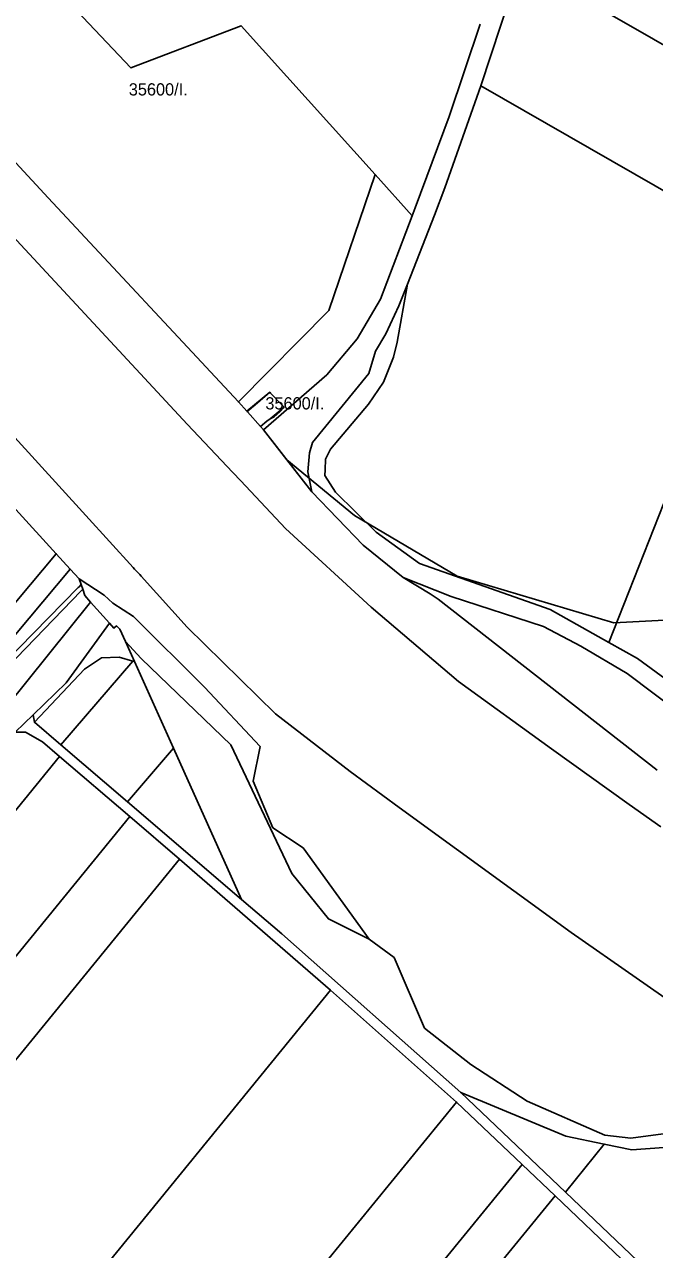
# Model space of a CAD drawing. Extents: x -545779 to -541342, y -1153413 to -1149956.
# Drawn here: x -543101 to -542843, y -1150751 to -1150249 of the extents above; entities that cross this region are included whole.
import ezdxf

# ---------------------------------------------------------------- set-up
doc = ezdxf.new("R2010")
doc.units = 0
for name, color, linetype in [('95560013', 7, 'Continuous'), ('95610013', 7, 'Continuous'), ('95630013', 7, 'Continuous'), ('95640013', 7, 'Continuous'), ('95660013', 7, 'Continuous')]:
    doc.layers.add(name, color=color, linetype=linetype)

msp = doc.modelspace()

# ---------------------------------------------------------------- linework, layer by layer
at = {"layer": '95560013'}
for points in [[(-543223.32, -1150177.07), (-543227.35, -1150172.67), (-543219.01, -1150174.06), (-543216.16, -1150173.5), (-543207.09, -1150171.73), (-543187.68, -1150162.8), (-543165.76, -1150152.71), (-543057.62, -1150266.96), (-543012.33, -1150249.67), (-542957.48, -1150310.69), (-542976.41, -1150366.39), (-543013.48, -1150403.82), (-543091.46, -1150320.27), (-543179.45, -1150224.97)], [(-542897.56, -1150224), (-542891.21, -1150204.63), (-542782.39, -1150267.04), (-542673.59, -1150329.44), (-542680.59, -1150348.45), (-542789.08, -1150286.22)], [(-542789.08, -1150286.22), (-542680.59, -1150348.45), (-542698.75, -1150397.83), (-542806.43, -1150336.07), (-542914.11, -1150274.31), (-542897.56, -1150224)], [(-542885.74, -1150488.88), (-542939.27, -1150470.05), (-542957.08, -1150457.18), (-542973.67, -1150440.8), (-542978.05, -1150433.99), (-542977.98, -1150431.6), (-542977.86, -1150427.24), (-542975.75, -1150423.15), (-542960.11, -1150404.77), (-542954.03, -1150395.7), (-542949.96, -1150385.51), (-542948.44, -1150379.28), (-542944.25, -1150355.53), (-542933.12, -1150327.25), (-542928.95, -1150316.13), (-542914.11, -1150274.31), (-542806.43, -1150336.07), (-542698.75, -1150397.83), (-542722.86, -1150463.35), (-542823.35, -1150405.71), (-542839.07, -1150445.37), (-542861.66, -1150502.34)], [(-543009.79, -1150407.92), (-543010.11, -1150407.57), (-543000.66, -1150399.9), (-543007.6, -1150405.91)], [(-543000.33, -1150400.24), (-542996.07, -1150404.62), (-542994.75, -1150405.99), (-543000.54, -1150410.75), (-543001.78, -1150411.78), (-543004.38, -1150413.91), (-543009.79, -1150407.92), (-543007.6, -1150405.91), (-543000.66, -1150399.9)], [(-543104.73, -1150447.88), (-543088.15, -1150466.06), (-543162.68, -1150554.86), (-543237.21, -1150643.67), (-543254.82, -1150626.72), (-543179.78, -1150537.3)], [(-542763.51, -1150562.3), (-542783.62, -1150552.52), (-542817.82, -1150532.5), (-542849.86, -1150508.94), (-542861.66, -1150502.34), (-542839.07, -1150445.37), (-542737.65, -1150503.54), (-542758.53, -1150560.29)], [(-543082.43, -1150472.34), (-543156.78, -1150560.93), (-543231.13, -1150649.52), (-543237.21, -1150643.67), (-543162.68, -1150554.86), (-543088.15, -1150466.06)], [(-543111.12, -1150513.04), (-543173.2, -1150597.05), (-543217.86, -1150645.08), (-543224.74, -1150652.49), (-543226.31, -1150654.16), (-543231.13, -1150649.52), (-543156.78, -1150560.93), (-543082.43, -1150472.34), (-543078.75, -1150476.37), (-543077.94, -1150478.69), (-543078.97, -1150479.78), (-543079.12, -1150479.93), (-543109.47, -1150510.9)], [(-543126.41, -1150566.98), (-543104.97, -1150539.21), (-543103.96, -1150539.21), (-543100.81, -1150539.2), (-543093.81, -1150543.17), (-543086.79, -1150549.18), (-543177.34, -1150659.99), (-543267.88, -1150770.8), (-543358.43, -1150881.61), (-543380.51, -1150876.41), (-543328.86, -1150811.29), (-543290.26, -1150766.2), (-543226.11, -1150690.02), (-543182.54, -1150636.07)], [(-543058.06, -1150573.75), (-543144.54, -1150679.58), (-543231.02, -1150785.42), (-543317.5, -1150891.25), (-543358.43, -1150881.61), (-543267.88, -1150770.8), (-543177.34, -1150659.99), (-543086.79, -1150549.18)], [(-543163.06, -1150744.64), (-543288.45, -1150898.09), (-543317.5, -1150891.25), (-543231.02, -1150785.42), (-543144.54, -1150679.58), (-543058.06, -1150573.75), (-543037.67, -1150591.19)], [(-543163.06, -1150744.64), (-543037.67, -1150591.19), (-542975.69, -1150644.9), (-543087.67, -1150781.95), (-543199.66, -1150919), (-543288.45, -1150898.09)], [(-543024.52, -1150813.68), (-543124.95, -1150936.58), (-543199.66, -1150919), (-543087.67, -1150781.95), (-542975.69, -1150644.9), (-542924.06, -1150690.74)], [(-542897.18, -1150716.29), (-542991.04, -1150831.15), (-543084.9, -1150946.01), (-543124.95, -1150936.58), (-543024.52, -1150813.68), (-542924.06, -1150690.74)], [(-543064.8, -1150950.74), (-543084.9, -1150946.01), (-542991.04, -1150831.15), (-542897.18, -1150716.29), (-542883.7, -1150729.1), (-542974.25, -1150839.92)], [(-542856.45, -1150755.01), (-542940.33, -1150857.67), (-543024.19, -1150960.3), (-543064.8, -1150950.74), (-542974.25, -1150839.92), (-542883.7, -1150729.1)]]:
    msp.add_lwpolyline(points, close=True, dxfattribs=at)
at = {"layer": '95610013'}
for points in [[(-543045.89, -1150516.18), (-543053.34, -1150509.02), (-543059.81, -1150502.04), (-543062.08, -1150497), (-543063.52, -1150495.61), (-543064.51, -1150496.55), (-543066.32, -1150494.52), (-543074.08, -1150485.82), (-543076.39, -1150483.13), (-543077.28, -1150480.58), (-543077.94, -1150478.69), (-543078.75, -1150476.37), (-543068.55, -1150482.98), (-543064.95, -1150486.26), (-543056.47, -1150491.74), (-543027.35, -1150520.68), (-543004.61, -1150545.08), (-543007.41, -1150559.24), (-542999.35, -1150578.34), (-542987.02, -1150586.47), (-542959.84, -1150623.97), (-542976.63, -1150615.62), (-542991.64, -1150597.02), (-543016.57, -1150544.34)], [(-543076.62, -1150513.27), (-543069.62, -1150508.7), (-543062.37, -1150508.36), (-543056.79, -1150509.99), (-543086.23, -1150544.4), (-543097.12, -1150535.08)], [(-543056.14, -1150510.18), (-543040.16, -1150545.65), (-543059, -1150567.68), (-543086.23, -1150544.4), (-543056.79, -1150509.99)], [(-543059, -1150567.68), (-543040.16, -1150545.65), (-543012.19, -1150607.72)], [(-542879.33, -1150704.7), (-542863.52, -1150707.95), (-542879.48, -1150727.6), (-542922.39, -1150686.8)], [(-542852.21, -1150710.28), (-542792.22, -1150705.95), (-542840.86, -1150764.31), (-542879.48, -1150727.6), (-542863.52, -1150707.95)]]:
    msp.add_lwpolyline(points, close=True, dxfattribs=at)
at = {"layer": '95630013'}
for points in [[(-542797.14, -1150676.99), (-542877.1, -1150621.25), (-542947.61, -1150569.95), (-542967.7, -1150555.26), (-542998.29, -1150531.61), (-543034.45, -1150496.06), (-543053.37, -1150475.24), (-543053.95, -1150474.59), (-543056.04, -1150472.29), (-543056.63, -1150471.65), (-543076, -1150450.32), (-543155.13, -1150363.61), (-543234.26, -1150276.9), (-543338.6, -1150169.04)], [(-543188.54, -1150247.11), (-543111.5, -1150330.01), (-543034.47, -1150412.91), (-543015.84, -1150432.69), (-543015.26, -1150433.31), (-543013.1, -1150435.6), (-543012.54, -1150436.2), (-542994.14, -1150455.73), (-542959.14, -1150487.92), (-542923.23, -1150518.4), (-542885.11, -1150545.91), (-542853.27, -1150568.8), (-542840.3, -1150577.96)]]:
    msp.add_lwpolyline(points, dxfattribs=at)
at = {"layer": '95640013'}
for points in [[(-542914.41, -1150249.01), (-542927.06, -1150286.9), (-542941.11, -1150324.36), (-542942.32, -1150327.56), (-542957.48, -1150310.69), (-543012.33, -1150249.67), (-543057.62, -1150266.96), (-543165.76, -1150152.71)], [(-543338.6, -1150169.04), (-543234.26, -1150276.9), (-543155.13, -1150363.61), (-543076, -1150450.32), (-543056.63, -1150471.65), (-543056.04, -1150472.29), (-543053.95, -1150474.59), (-543053.37, -1150475.24), (-543034.45, -1150496.06), (-542998.29, -1150531.61), (-542967.7, -1150555.26), (-542947.61, -1150569.95), (-542877.1, -1150621.25), (-542797.14, -1150676.99)], [(-543179.45, -1150224.97), (-543091.46, -1150320.27), (-543013.48, -1150403.82), (-543010.11, -1150407.57), (-543009.79, -1150407.92), (-543004.38, -1150413.91), (-543003.17, -1150415.25), (-542983.39, -1150440.67), (-542962.35, -1150462.51), (-542945.93, -1150475.79), (-542934.91, -1150482.45), (-542931.65, -1150484.68), (-542841.86, -1150554.66)], [(-542897.56, -1150224), (-542914.11, -1150274.31), (-542928.95, -1150316.13), (-542933.12, -1150327.25), (-542944.25, -1150355.53), (-542947.8, -1150364.52), (-542953.1, -1150375.9), (-542957.36, -1150383.09), (-542960.1, -1150392.22), (-542983.11, -1150420.46), (-542984.39, -1150424.73), (-542985.04, -1150432.41), (-542983.39, -1150440.67), (-543003.17, -1150415.25), (-542977.28, -1150392.72), (-542964.77, -1150377.98), (-542955.27, -1150361.66), (-542942.32, -1150327.56), (-542941.11, -1150324.36), (-542927.06, -1150286.9), (-542914.41, -1150249.01)], [(-542840.3, -1150577.96), (-542853.27, -1150568.8), (-542885.11, -1150545.91), (-542923.23, -1150518.4), (-542959.14, -1150487.92), (-542994.14, -1150455.73), (-543012.54, -1150436.2), (-543013.1, -1150435.6), (-543015.26, -1150433.31), (-543015.84, -1150432.69), (-543034.47, -1150412.91), (-543111.5, -1150330.01), (-543188.54, -1150247.11)], [(-542822.11, -1150539.26), (-542854.19, -1150515.06), (-542873.16, -1150503.85), (-542888.45, -1150495.87), (-542926.35, -1150483.61), (-542945.93, -1150475.79), (-542962.35, -1150462.51), (-542983.39, -1150440.67), (-542985.04, -1150432.41), (-542984.39, -1150424.73), (-542983.11, -1150420.46), (-542960.1, -1150392.22), (-542957.36, -1150383.09), (-542953.1, -1150375.9), (-542947.8, -1150364.52), (-542944.25, -1150355.53), (-542948.44, -1150379.28), (-542949.96, -1150385.51), (-542954.03, -1150395.7), (-542960.11, -1150404.77), (-542975.75, -1150423.15), (-542977.86, -1150427.24), (-542977.98, -1150431.6), (-542978.05, -1150433.99), (-542973.67, -1150440.8), (-542957.08, -1150457.18), (-542939.27, -1150470.05), (-542885.74, -1150488.88), (-542861.66, -1150502.34), (-542849.86, -1150508.94), (-542817.82, -1150532.5)], [(-542839.4, -1150703.66), (-542852.6, -1150705.43), (-542863.28, -1150704.32), (-542895.09, -1150690.3), (-542918.2, -1150675.26), (-542937.22, -1150660.42), (-542949.72, -1150631.43), (-542959.84, -1150623.97), (-542987.02, -1150586.47), (-542999.35, -1150578.34), (-543007.41, -1150559.24), (-543004.61, -1150545.08), (-543027.35, -1150520.68), (-543056.47, -1150491.74), (-543064.95, -1150486.26), (-543068.55, -1150482.98), (-543078.75, -1150476.37), (-543082.43, -1150472.34), (-543088.15, -1150466.06), (-543104.73, -1150447.88)], [(-543109.47, -1150510.9), (-543079.12, -1150479.93), (-543078.97, -1150479.78), (-543077.94, -1150478.69), (-543077.28, -1150480.58), (-543077.98, -1150481.28), (-543108.19, -1150512.45)], [(-542841.86, -1150554.66), (-542931.65, -1150484.68), (-542934.91, -1150482.45), (-542945.93, -1150475.79), (-542926.35, -1150483.61), (-542888.45, -1150495.87), (-542873.16, -1150503.85), (-542854.19, -1150515.06), (-542822.11, -1150539.26)], [(-543296.93, -1150758.24), (-543245.84, -1150696.55), (-543232.51, -1150663.7), (-543229.59, -1150660.58), (-543226.01, -1150656.76), (-543223.33, -1150653.9), (-543220.18, -1150650.51), (-543194.48, -1150635.21), (-543134.28, -1150560.52), (-543074.08, -1150485.82), (-543066.32, -1150494.52), (-543084.05, -1150518.91), (-543097.63, -1150532.08), (-543104.97, -1150539.21), (-543112.93, -1150546.93), (-543157.53, -1150600.92), (-543202.13, -1150654.9), (-543240.31, -1150701.11), (-543291.34, -1150762.87)], [(-542792.22, -1150705.95), (-542852.21, -1150710.28), (-542863.52, -1150707.95), (-542879.33, -1150704.7), (-542922.39, -1150686.8), (-542995.69, -1150621.83), (-543012.19, -1150607.72), (-543040.16, -1150545.65), (-543056.14, -1150510.18), (-543059.81, -1150502.04), (-543053.34, -1150509.02), (-543045.89, -1150516.18), (-543016.57, -1150544.34), (-542991.64, -1150597.02), (-542976.63, -1150615.62), (-542959.84, -1150623.97), (-542949.72, -1150631.43), (-542937.22, -1150660.42), (-542918.2, -1150675.26), (-542895.09, -1150690.3), (-542863.28, -1150704.32), (-542852.6, -1150705.43), (-542839.4, -1150703.66)], [(-542832.51, -1150777.76), (-542856.45, -1150755.01), (-542883.7, -1150729.1), (-542897.18, -1150716.29), (-542924.06, -1150690.74), (-542975.69, -1150644.9), (-543037.67, -1150591.19), (-543058.06, -1150573.75), (-543086.79, -1150549.18), (-543093.81, -1150543.17), (-543100.81, -1150539.2), (-543103.96, -1150539.21), (-543104.97, -1150539.21), (-543097.63, -1150532.08), (-543097.12, -1150535.08), (-543086.23, -1150544.4), (-543059, -1150567.68), (-543012.19, -1150607.72), (-542995.69, -1150621.83), (-542922.39, -1150686.8), (-542879.48, -1150727.6), (-542840.86, -1150764.31)]]:
    msp.add_lwpolyline(points, dxfattribs=at)
for points in [[(-543000.33, -1150400.24), (-543000.66, -1150399.9), (-543010.11, -1150407.57), (-543013.48, -1150403.82), (-542976.41, -1150366.39), (-542957.48, -1150310.69), (-542942.32, -1150327.56), (-542955.27, -1150361.66), (-542964.77, -1150377.98), (-542977.28, -1150392.72), (-543003.17, -1150415.25), (-543004.38, -1150413.91), (-543001.78, -1150411.78), (-543000.54, -1150410.75), (-542998.79, -1150409.94), (-542996.51, -1150407.89), (-542994.75, -1150405.99), (-542996.07, -1150404.62)], [(-543000.54, -1150410.75), (-542994.75, -1150405.99), (-542996.51, -1150407.89), (-542998.79, -1150409.94)], [(-543076.39, -1150483.13), (-543074.08, -1150485.82), (-543134.28, -1150560.52), (-543194.48, -1150635.21), (-543220.18, -1150650.51), (-543171.65, -1150598.32), (-543108.19, -1150512.45), (-543077.98, -1150481.28), (-543077.28, -1150480.58)], [(-543084.05, -1150518.91), (-543066.32, -1150494.52), (-543064.51, -1150496.55), (-543063.52, -1150495.61), (-543062.08, -1150497), (-543059.81, -1150502.04), (-543056.14, -1150510.18), (-543056.79, -1150509.99), (-543062.37, -1150508.36), (-543069.62, -1150508.7), (-543076.62, -1150513.27), (-543097.12, -1150535.08), (-543097.63, -1150532.08)]]:
    msp.add_lwpolyline(points, close=True, dxfattribs=at)
at = {"layer": '95660013'}
for points in [[(-543012.33, -1150249.67), (-542957.48, -1150310.69), (-542976.41, -1150366.39), (-543013.48, -1150403.82), (-543091.46, -1150320.27), (-543179.45, -1150224.97), (-543223.32, -1150177.07), (-543227.35, -1150172.67), (-543219.01, -1150174.06), (-543216.16, -1150173.5), (-543207.09, -1150171.73), (-543187.68, -1150162.8), (-543165.76, -1150152.71), (-543057.62, -1150266.96)], [(-543000.66, -1150399.9), (-543000.33, -1150400.24), (-542996.07, -1150404.62), (-542994.75, -1150405.99), (-542996.51, -1150407.89), (-542998.79, -1150409.94), (-543000.54, -1150410.75), (-543001.78, -1150411.78), (-543004.38, -1150413.91), (-543009.79, -1150407.92), (-543010.11, -1150407.57)], [(-543000.33, -1150400.24), (-543000.66, -1150399.9), (-543010.11, -1150407.57), (-543009.79, -1150407.92), (-543004.38, -1150413.91), (-543001.78, -1150411.78), (-543000.54, -1150410.75), (-542998.79, -1150409.94), (-542996.51, -1150407.89), (-542994.75, -1150405.99), (-542996.07, -1150404.62)]]:
    msp.add_lwpolyline(points, close=True, dxfattribs=at)
for points in [[(-543179.45, -1150224.97), (-543091.46, -1150320.27), (-543013.48, -1150403.82), (-542976.41, -1150366.39), (-542957.48, -1150310.69), (-543012.33, -1150249.67), (-543057.62, -1150266.96), (-543165.76, -1150152.71)], [(-542805.105, -1150491.449), (-542859.653, -1150494.32), (-542923.77, -1150475.181), (-542965.877, -1150450.299), (-542993.592, -1150427.56), (-543003.17, -1150415.25), (-542977.28, -1150392.72), (-542964.77, -1150377.98), (-542955.27, -1150361.66), (-542942.32, -1150327.56), (-542941.11, -1150324.36), (-542927.06, -1150286.9), (-542914.41, -1150249.01)], [(-542914.41, -1150249.01), (-542927.06, -1150286.9), (-542941.11, -1150324.36), (-542942.32, -1150327.56), (-542955.27, -1150361.66), (-542964.77, -1150377.98), (-542977.28, -1150392.72), (-543003.17, -1150415.25), (-542993.592, -1150427.56), (-542983.39, -1150440.67), (-542962.35, -1150462.51), (-542945.93, -1150475.79), (-542934.91, -1150482.45), (-542931.65, -1150484.68), (-542841.86, -1150554.66)], [(-542841.86, -1150554.66), (-542931.65, -1150484.68), (-542934.91, -1150482.45), (-542945.93, -1150475.79), (-542962.35, -1150462.51), (-542983.39, -1150440.67), (-542993.592, -1150427.56), (-542993.592, -1150427.56), (-542965.877, -1150450.299), (-542923.77, -1150475.181), (-542859.653, -1150494.32), (-542805.105, -1150491.449)], [(-543104.73, -1150447.88), (-543088.15, -1150466.06), (-543082.43, -1150472.34), (-543078.75, -1150476.37), (-543068.55, -1150482.98), (-543064.95, -1150486.26), (-543056.47, -1150491.74), (-543027.35, -1150520.68), (-543004.61, -1150545.08), (-543007.41, -1150559.24), (-542999.35, -1150578.34), (-542987.02, -1150586.47), (-542959.84, -1150623.97), (-542976.63, -1150615.62), (-542991.64, -1150597.02), (-543016.57, -1150544.34), (-543045.89, -1150516.18), (-543053.34, -1150509.02), (-543059.81, -1150502.04), (-543056.14, -1150510.18), (-543040.16, -1150545.65), (-543012.19, -1150607.72), (-542995.69, -1150621.83), (-542922.39, -1150686.8), (-542879.33, -1150704.7), (-542863.52, -1150707.95), (-542852.21, -1150710.28), (-542792.22, -1150705.95)], [(-542792.22, -1150705.95), (-542852.21, -1150710.28), (-542863.52, -1150707.95), (-542879.33, -1150704.7), (-542922.39, -1150686.8), (-542995.69, -1150621.83), (-543012.19, -1150607.72), (-543040.16, -1150545.65), (-543056.14, -1150510.18), (-543059.81, -1150502.04), (-543053.34, -1150509.02), (-543045.89, -1150516.18), (-543016.57, -1150544.34), (-542991.64, -1150597.02), (-542976.63, -1150615.62), (-542959.84, -1150623.97), (-542987.02, -1150586.47), (-542999.35, -1150578.34), (-543007.41, -1150559.24), (-543004.61, -1150545.08), (-543027.35, -1150520.68), (-543056.47, -1150491.74), (-543064.95, -1150486.26), (-543068.55, -1150482.98), (-543078.75, -1150476.37), (-543082.43, -1150472.34), (-543088.15, -1150466.06), (-543104.73, -1150447.88)]]:
    msp.add_lwpolyline(points, dxfattribs=at)

# ---------------------------------------------------------------- texts
for p in [(-543058.435, -1150278.265), (-543002.444, -1150406.905)]:
    msp.add_text('35600/I.', height=5, rotation=0, dxfattribs=at).set_placement(p)

doc.saveas('drawing.dxf')
